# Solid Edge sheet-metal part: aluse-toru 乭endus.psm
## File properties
Title: aluse-toru ühendus
Author: Stella-Marii
Template: Iso Metric Sheet Metal.psm
Last saved by: Stella-Marii
Revision: 3
Application: Solid Edge
Density: 7833,000 kg/m^3
Accuracy: 0,990
Material Thickness: 3,00 mm
Bend Radius: 1,00 mm
Relief Width: 1,00 mm
Relief Length: 0,00 mm
Neutral Factor: 0,330
Minimum Arc Length: 0,10 mm
Deviational Tolerance: 0,10 mm
Username: Stella-Marii
Document Number: 13
Material: Steel, structural
Face Style: Steel
Fill Style: ANSI32(Steel)
Virtual Style: Brushed steel
Grouping: Metals\Steel
LibraryName: Materials
Coef. of Thermal Exp: 1.3e-05
Thermal Conductivity: 32.0
Specific Heat: 481.0
Modulus of Elasticity: 199947953000.0
Poisson's Ratio: 0.29
Yield Stress: 262000766.0
Ultimate Stress: 358527364.0
Elongation: 0.0
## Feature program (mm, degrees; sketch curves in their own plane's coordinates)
base tab "unnamed BaseTab 1"
break corner "BreakCorner_2"  SetBackValue1 = 40 mm
sheet metal cutout "SheetMetalCutout_1"
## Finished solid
Body 1: solid body, 9 faces, 20 edges, 12 vertices.
  Faces by surface: plane 6, cylinder 3
  Edges by curve: line 14, circle 6
Bounding box of the edges (mm): 3.000 x 294.000 x 112.000, from (0, -147, 0) to (3, 147, 112).
Cylindrical faces by radius (mm): R22.75 x1, R40 x2
Planar faces by outward normal: +x 1, +z 1, -x 1, -z 1, oblique 2
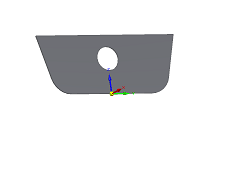
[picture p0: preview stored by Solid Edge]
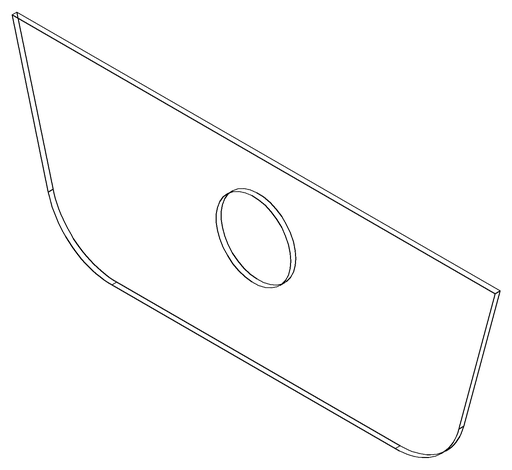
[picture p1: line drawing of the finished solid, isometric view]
